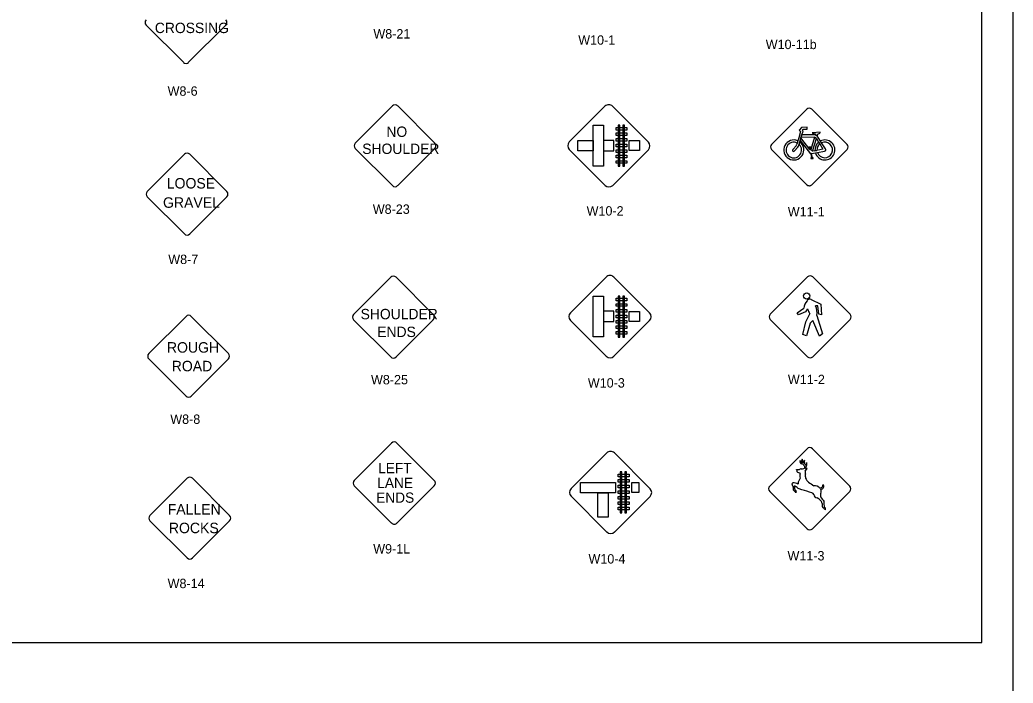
# Model space of a CAD drawing. Extents: x 42133 to 45533, y 41351 to 47951.
# Drawn here: x 44739 to 45533, y 46869 to 47400 of the extents above; entities that cross this region are included whole.
import ezdxf

# ---------------------------------------------------------------- set-up
doc = ezdxf.new("R2010")
doc.units = 0
for name, color, linetype in [('#plot_shape', 7, 'Continuous'), ('P_ODOT_PLAN_Border', 7, 'Continuous'), ('P_TRAF_SIGN_SignDetails', 7, 'Continuous')]:
    doc.layers.add(name, color=color, linetype=linetype)

msp = doc.modelspace()

# ---------------------------------------------------------------- linework, layer by layer
at = {"layer": '#plot_shape'}
msp.add_lwpolyline([(43833.34, 46851.35), (45533.34, 46851.35), (45533.34, 47951.35), (43833.34, 47951.35)], close=True, dxfattribs=at)
at = {"layer": 'P_ODOT_PLAN_Border'}
msp.add_lwpolyline([(43908.34, 46901.35), (45508.34, 46901.35), (45508.34, 47901.35), (43908.34, 47901.35)], close=True, dxfattribs=at)
at = {"layer": 'P_TRAF_SIGN_SignDetails'}
for p, q in [((44839.93, 47395.35), (44869.67, 47365.61)), ((44873.91, 47365.61), (44903.66, 47395.35)), ((45036.83, 47330.68), (45007.09, 47300.94)), ((45070.82, 47300.94), (45041.08, 47330.68)), ((45178.37, 47301.91), (45206.89, 47330.44)), ((45213.01, 47330.43), (45241.6, 47301.84)), ((45368.24, 47328.17), (45340.04, 47299.96)), ((45400.48, 47299.96), (45372.26, 47328.17)), ((45363.35, 47310.21), (45361.84, 47305.33)), ((45364.11, 47313.34), (45362.29, 47311.46)), ((45362.29, 47311.46), (45363.35, 47310.21)), ((45368.51, 47313.61), (45364.11, 47313.34)), ((45364.38, 47307.62), (45365.3, 47310.61)), ((45364.66, 47311.38), (45365.29, 47312.03)), ((45365.3, 47310.61), (45364.66, 47311.38)), ((45365.29, 47312.03), (45368.6, 47312.24)), ((45368.6, 47312.24), (45368.51, 47313.61)), ((45378.95, 47309.66), (45372.82, 47309.33)), ((45375.25, 47308.32), (45375.05, 47307.56)), ((45376.67, 47306.83), (45377.09, 47308.42)), ((45378.95, 47309.66), (45378.95, 47309.66)), ((45360.65, 47301.03), (45360.4, 47300.14)), ((45361.15, 47302.83), (45360.65, 47301.03)), ((45361.84, 47305.31), (45361.15, 47302.83)), ((45362.17, 47300), (45362.71, 47301.93)), ((45362.2, 47300.01), (45362.71, 47301.93)), ((45362.71, 47301.93), (45363.05, 47303.16)), ((45363.05, 47303.16), (45363.65, 47305.24)), ((45363.65, 47305.24), (45363.05, 47303.16)), ((45363.05, 47303.16), (45371.3, 47292.37)), ((45363.65, 47305.24), (45363.84, 47305.88)), ((45370.81, 47295.89), (45363.65, 47305.24)), ((45363.84, 47305.88), (45364.38, 47307.62)), ((45364.38, 47307.62), (45363.84, 47305.88)), ((45363.84, 47305.88), (45374.54, 47305.81)), ((45375.05, 47307.56), (45364.38, 47307.62)), ((45374.54, 47305.81), (45371.51, 47295.82)), ((45372.93, 47294.47), (45376, 47304.57)), ((45376, 47304.57), (45374.54, 47305.81)), ((45374.54, 47305.81), (45376, 47304.57)), ((45375.05, 47307.56), (45376.67, 47306.83)), ((45376.67, 47306.83), (45375.05, 47307.56)), ((45376, 47304.57), (45377.8, 47301.67)), ((45379.32, 47302.58), (45376.67, 47306.83)), ((45377.77, 47301.71), (45378.65, 47300.3)), ((45377.8, 47301.67), (45378.64, 47300.33)), ((45378.64, 47300.33), (45377.8, 47301.67)), ((45378.64, 47300.33), (45381.25, 47296.13)), ((45378.65, 47300.3), (45378.64, 47300.33)), ((45380.14, 47301.25), (45379.32, 47302.58)), ((45380.14, 47301.25), (45379.32, 47302.58)), ((45383.21, 47296.3), (45380.14, 47301.25)), ((45380.14, 47301.23), (45380.14, 47301.25)), ((45007.09, 47296.7), (45036.84, 47266.96)), ((45041.08, 47266.96), (45070.82, 47296.7)), ((45206.96, 47267.2), (45178.37, 47295.79)), ((45241.6, 47295.71), (45213.08, 47267.2)), ((45340.04, 47295.94), (45368.24, 47267.73)), ((45359.79, 47298.76), (45357.3, 47296.03)), ((45358.58, 47294.81), (45361.25, 47297.76)), ((45362.03, 47299.49), (45362.17, 47300)), ((45371.81, 47297.65), (45369.92, 47297.65)), ((45369.92, 47297.65), (45369.92, 47297.26)), ((45369.92, 47297.26), (45370.54, 47297.26)), ((45370.54, 47297.26), (45370.81, 47295.89)), ((45370.81, 47295.89), (45371.51, 47295.82)), ((45371.51, 47295.82), (45370.81, 47295.89)), ((45371.51, 47295.82), (45371.23, 47297.26)), ((45371.23, 47297.26), (45371.81, 47297.26)), ((45371.45, 47292.39), (45371.3, 47292.37)), ((45372.18, 47292.54), (45371.45, 47292.39)), ((45371.45, 47292.39), (45372.08, 47289.08)), ((45371.51, 47295.82), (45372.93, 47294.47)), ((45372.93, 47294.47), (45371.51, 47295.82)), ((45371.81, 47297.26), (45371.81, 47297.65)), ((45372.18, 47292.54), (45375.16, 47293.14)), ((45372.83, 47289.1), (45372.18, 47292.54)), ((45372.26, 47267.73), (45400.48, 47295.94)), ((45374.8, 47294.85), (45372.93, 47294.47)), ((45376.41, 47295.17), (45374.8, 47294.85)), ((45374.8, 47294.85), (45376.41, 47295.17)), ((45375.16, 47293.14), (45376.78, 47293.45)), ((45375.16, 47293.14), (45376.78, 47293.45)), ((45381.25, 47296.13), (45376.41, 47295.17)), ((45376.78, 47293.45), (45382.45, 47294.58)), ((44870.48, 47292.01), (44840.74, 47262.27)), ((44904.47, 47262.27), (44874.72, 47292.01)), ((45372.08, 47289.08), (45371.52, 47289.08)), ((45371.52, 47289.08), (45371.52, 47288.77)), ((45371.52, 47288.77), (45373.39, 47288.77)), ((45373.39, 47289.1), (45372.83, 47289.1)), ((45373.39, 47288.77), (45373.39, 47289.1)), ((44840.74, 47258.03), (44870.48, 47228.29)), ((44874.72, 47228.29), (44904.47, 47258.03)), ((45035.54, 47193.66), (45005.8, 47163.92)), ((45069.52, 47163.92), (45039.78, 47193.66)), ((45179.3, 47165.25), (45207.82, 47193.78)), ((45213.95, 47193.77), (45242.54, 47165.18)), ((45368.87, 47193.88), (45339.05, 47164.08)), ((45368.87, 47193.88), (45339.05, 47164.08)), ((45402.92, 47164.08), (45373.12, 47193.88)), ((45402.92, 47164.08), (45373.12, 47193.88)), ((45371.75, 47175.74), (45371.75, 47175.75)), ((45371.75, 47175.75), (45379.58, 47172.02)), ((45371.75, 47175.74), (45371.75, 47175.75)), ((45371.75, 47175.74), (45371.75, 47175.75)), ((45371.75, 47175.75), (45379.58, 47172.02)), ((45371.75, 47175.74), (45371.75, 47175.75)), ((45360.69, 47165.09), (45366.04, 47168.95)), ((45360.69, 47165.09), (45366.04, 47168.95)), ((45367.34, 47165.96), (45361.63, 47163.67)), ((45367.34, 47165.96), (45361.63, 47163.67)), ((45368.92, 47168.36), (45367.34, 47165.96)), ((45368.92, 47168.36), (45367.34, 47165.96)), ((45377.09, 47170.77), (45375.21, 47170.91)), ((45377.09, 47170.77), (45375.21, 47170.91)), ((45377.97, 47164), (45377.09, 47170.77)), ((45377.97, 47164), (45377.09, 47170.77)), ((45379.58, 47172.02), (45379.97, 47163.65)), ((45379.58, 47172.02), (45379.97, 47163.65)), ((44871.79, 47162.32), (44842.05, 47132.57)), ((44905.77, 47132.57), (44876.03, 47162.32)), ((45005.8, 47159.68), (45035.54, 47129.93)), ((45039.78, 47129.93), (45069.52, 47159.68)), ((45207.89, 47130.54), (45179.3, 47159.12)), ((45242.54, 47159.05), (45214.02, 47130.54)), ((45339.05, 47159.83), (45368.87, 47130.02)), ((45339.05, 47159.83), (45368.87, 47130.02)), ((45361.63, 47163.67), (45360.69, 47165.09)), ((45361.63, 47163.67), (45360.69, 47165.09)), ((45365.07, 47147.79), (45367.53, 47158)), ((45365.07, 47147.79), (45367.53, 47158)), ((45367.53, 47158), (45370.76, 47164.47)), ((45367.53, 47158), (45370.76, 47164.47)), ((45373.06, 47159.05), (45370.98, 47156.84)), ((45373.06, 47159.05), (45370.98, 47156.84)), ((45378.52, 47146.46), (45373.06, 47159.05)), ((45378.52, 47146.46), (45373.06, 47159.05)), ((45373.12, 47130.02), (45402.92, 47159.83)), ((45373.12, 47130.02), (45402.92, 47159.83)), ((45376.32, 47163.02), (45380.94, 47148.31)), ((45376.32, 47163.02), (45380.94, 47148.31)), ((45379.97, 47163.65), (45377.97, 47164)), ((45379.97, 47163.65), (45377.97, 47164)), ((45370.98, 47156.84), (45368.1, 47146.91)), ((45370.98, 47156.84), (45368.1, 47146.91)), ((45368.1, 47146.91), (45365.07, 47147.79)), ((45368.1, 47146.91), (45365.07, 47147.79)), ((45380.94, 47148.31), (45378.52, 47146.46)), ((45380.94, 47148.31), (45378.52, 47146.46)), ((44842.05, 47128.34), (44871.79, 47098.59)), ((44876.03, 47098.59), (44905.77, 47128.34)), ((45006.41, 47031.17), (45036.26, 47061.02)), ((45040.53, 47061.02), (45070.37, 47031.17)), ((45368.51, 47056.5), (45338.63, 47026.62)), ((45402.65, 47026.62), (45372.78, 47056.5)), ((45179.77, 47024.57), (45208.3, 47053.09)), ((45214.42, 47053.09), (45243.01, 47024.5)), ((45366.4, 47047.15), (45366.4, 47047.15)), ((45363.8, 47040.43), (45363.62, 47040.43)), ((44872.7, 47032.8), (44842.96, 47003.06)), ((44906.68, 47003.06), (44876.94, 47032.8)), ((45036.26, 46997.05), (45006.41, 47026.9)), ((45070.37, 47026.9), (45040.53, 46997.05)), ((45338.63, 47022.37), (45368.52, 46992.49)), ((45372.78, 46992.49), (45402.65, 47022.37)), ((45208.36, 46989.85), (45179.77, 47018.44)), ((45243.01, 47018.37), (45214.49, 46989.85)), ((44842.96, 46998.82), (44872.7, 46969.08)), ((44876.94, 46969.08), (44906.68, 46998.82))]:
    msp.add_line(p, q, dxfattribs=at)
for points in [[(45197.5, 47315.28), (45205.68, 47315.28), (45205.68, 47282.58), (45197.5, 47282.58)], [(45215.71, 47313.51), (45224.47, 47313.51), (45224.47, 47311.44), (45215.71, 47311.44)], [(45215.71, 47309.13), (45224.47, 47309.13), (45224.47, 47307.06), (45215.71, 47307.06)], [(45218.72, 47315.3), (45217.35, 47315.3), (45217.35, 47282.5), (45218.72, 47282.5)], [(45222.45, 47315.3), (45221.08, 47315.3), (45221.08, 47282.5), (45222.45, 47282.5)], [(45185.12, 47303.1), (45197.5, 47303.1), (45197.5, 47294.91), (45185.12, 47294.91)], [(45205.68, 47294.91), (45213.97, 47294.91), (45213.97, 47303.1), (45205.68, 47303.1)], [(45215.71, 47304.56), (45224.47, 47304.56), (45224.47, 47302.49), (45215.71, 47302.49)], [(45234.42, 47294.97), (45226.13, 47294.97), (45226.13, 47303.05), (45234.42, 47303.05)], [(45215.71, 47300.04), (45224.47, 47300.04), (45224.47, 47297.96), (45215.71, 47297.96)], [(45215.71, 47295.61), (45224.47, 47295.61), (45224.47, 47293.54), (45215.71, 47293.54)], [(45215.71, 47291.36), (45224.47, 47291.36), (45224.47, 47289.29), (45215.71, 47289.29)], [(45215.71, 47286.93), (45224.47, 47286.93), (45224.47, 47284.86), (45215.71, 47284.86)], [(45197.5, 47178.62), (45205.68, 47178.62), (45205.68, 47145.92), (45197.5, 47145.92)], [(45215.71, 47176.85), (45224.47, 47176.85), (45224.47, 47174.78), (45215.71, 47174.78)], [(45218.72, 47178.64), (45217.35, 47178.64), (45217.35, 47145.84), (45218.72, 47145.84)], [(45222.45, 47178.64), (45221.08, 47178.64), (45221.08, 47145.84), (45222.45, 47145.84)], [(45205.68, 47158.25), (45213.97, 47158.25), (45213.97, 47166.44), (45205.68, 47166.44)], [(45215.71, 47172.47), (45224.47, 47172.47), (45224.47, 47170.4), (45215.71, 47170.4)], [(45215.71, 47167.9), (45224.47, 47167.9), (45224.47, 47165.83), (45215.71, 47165.83)], [(45234.42, 47158.3), (45226.13, 47158.3), (45226.13, 47166.39), (45234.42, 47166.39)], [(45215.71, 47163.38), (45224.47, 47163.38), (45224.47, 47161.3), (45215.71, 47161.3)], [(45215.71, 47158.95), (45224.47, 47158.95), (45224.47, 47156.88), (45215.71, 47156.88)], [(45215.71, 47154.7), (45224.47, 47154.7), (45224.47, 47152.63), (45215.71, 47152.63)], [(45215.71, 47150.27), (45224.47, 47150.27), (45224.47, 47148.2), (45215.71, 47148.2)], [(45217.46, 47036.16), (45226.21, 47036.16), (45226.21, 47034.1), (45217.46, 47034.1)], [(45217.46, 47031.79), (45226.21, 47031.79), (45226.21, 47029.71), (45217.46, 47029.71)], [(45220.47, 47037.95), (45219.1, 47037.95), (45219.1, 47005.16), (45220.47, 47005.16)], [(45224.19, 47037.95), (45222.83, 47037.95), (45222.83, 47005.16), (45224.19, 47005.16)], [(45187.24, 47021.29), (45187.24, 47029.47), (45215.28, 47029.47), (45215.28, 47021.29)], [(45217.46, 47027.22), (45226.21, 47027.22), (45226.21, 47025.14), (45217.46, 47025.14)], [(45217.46, 47022.69), (45226.21, 47022.69), (45226.21, 47020.62), (45217.46, 47020.62)], [(45233.95, 47021.39), (45228.42, 47021.39), (45228.42, 47029.47), (45233.95, 47029.47)], [(45201.19, 47021.29), (45209.38, 47021.29), (45209.38, 47001.76), (45201.19, 47001.76)], [(45217.46, 47018.27), (45226.21, 47018.27), (45226.21, 47016.19), (45217.46, 47016.19)], [(45217.46, 47014.02), (45226.21, 47014.02), (45226.21, 47011.95), (45217.46, 47011.95)], [(45217.46, 47009.59), (45226.21, 47009.59), (45226.21, 47007.52), (45217.46, 47007.52)]]:
    msp.add_lwpolyline(points, close=True, dxfattribs=at)
msp.add_circle((45368.26, 47178.69), 2.49, dxfattribs=at)
msp.add_circle((45368.26, 47178.69), 2.49, dxfattribs=at)
for centre, radius, start, end in [((44842.04, 47397.47), 3, 135, 225), ((44901.54, 47397.47), 3, 315, 45), ((44871.79, 47367.72), 3, 225, 315), ((45038.95, 47328.56), 3, 45, 135), ((45209.95, 47327.37), 4.33, 44.98912, 135), ((45370.26, 47326.16), 2.84, 45, 135), ((45372.89, 47309.16), 0.159, 98.17141, 240.58115), ((45376.81, 47318.22), 10.02, 246.22898, 261.11843), ((45377.22, 47310.54), 2.12, 266.63911, 329.73105), ((45378.92, 47309.52), 0.138, 336.8194, 78.51671), ((45009.21, 47298.82), 3, 135, 225), ((45068.7, 47298.82), 3, 315, 45), ((45181.43, 47298.85), 4.33, 135, 225), ((45238.54, 47298.78), 4.33, 315, 44.99846), ((45357.94, 47295.5), 8, 66.40234, 53.46049), ((45357.95, 47295.43), 6.24, 64.41042, 47.13868), ((45382.81, 47295.5), 8, 129.01304, 184.65487), ((45382.81, 47295.5), 8, 197.6727, 116.33071), ((45382.66, 47295.52), 6.24, 129.99723, 183.4253), ((45382.66, 47295.52), 6.24, 199.3058, 113.79242), ((44872.6, 47289.9), 3, 45, 135), ((45342.05, 47297.95), 2.84, 135, 225), ((45357.77, 47295.23), 0.897, 122.87626, 330.77195), ((45326.47, 47314.32), 36.77, 334.95815, 337.32166), ((45328.1, 47313.66), 36.77, 334.41845, 337.32166), ((45382.66, 47295.52), 0.955, 257.41231, 57.06777), ((45398.47, 47297.95), 2.84, 315, 45), ((44842.85, 47260.15), 3, 135, 225), ((44902.35, 47260.15), 3, 315, 45), ((45038.95, 47269.07), 3, 225, 315), ((45210.02, 47270.26), 4.33, 225, 315), ((45370.26, 47269.74), 2.84, 225, 296.51146), ((45370.26, 47269.74), 2.84, 225, 315), ((44872.6, 47230.4), 3, 225, 315), ((45037.66, 47191.54), 3, 45, 135), ((45210.88, 47190.71), 4.33, 44.98912, 135), ((45370.99, 47191.76), 3.01, 45, 135), ((45370.99, 47191.76), 3.01, 45, 135), ((45377.46, 47167.77), 11.48, 141.49763, 174.1516), ((45377.46, 47167.77), 11.48, 141.49763, 174.1516), ((45371.86, 47172.6), 4.11, 133.03994, 145.50454), ((45371.86, 47172.6), 4.11, 133.03994, 145.50454), ((45370.52, 47173.55), 2.52, 60.67847, 125.47574), ((45370.52, 47173.55), 2.52, 60.67847, 125.47574), ((45182.36, 47162.19), 4.33, 135, 225), ((45401.96, 47181.56), 35.58, 201.7818, 208.71131), ((45401.96, 47181.56), 35.58, 201.7818, 208.71131), ((45363.64, 47165.25), 12.87, 349.98612, 26.05989), ((45363.64, 47165.25), 12.87, 349.98612, 26.05989), ((44873.91, 47160.2), 3, 45, 135), ((45007.91, 47161.8), 3, 135, 225), ((45067.4, 47161.8), 3, 315, 45), ((45239.47, 47162.12), 4.33, 315, 44.99846), ((45341.18, 47161.95), 3.01, 135, 225), ((45341.18, 47161.95), 3.01, 135, 225), ((45400.8, 47161.95), 3.01, 315, 45), ((45400.8, 47161.95), 3.01, 315, 45), ((44844.16, 47130.45), 3, 135, 225), ((44903.65, 47130.45), 3, 315, 45), ((45037.66, 47132.05), 3, 225, 315), ((45210.95, 47133.6), 4.33, 225, 315), ((45370.99, 47132.14), 3.01, 225, 315), ((45370.99, 47132.14), 3.01, 225, 315), ((44873.91, 47100.71), 3, 225, 315), ((45038.39, 47058.88), 3.02, 45, 135), ((45211.35, 47050.03), 4.33, 44.98912, 135), ((45370.64, 47054.38), 3.01, 45, 135), ((45365.13, 47046.46), 2.3, 162.00661, 251.6619), ((45365.14, 47047.35), 2.21, 184.61833, 248.44889), ((45368.33, 47046.5), 4.18, 160.63849, 196.77489), ((45364.94, 47047.18), 0.9, 104.4916, 128.6904), ((45368.47, 47047.56), 3.79, 172.48527, 222.52538), ((45367.22, 47045.68), 1.68, 119.26155, 203.94207), ((45373.82, 47046.15), 7.49, 172.3359, 186.45015), ((45359.27, 47039.96), 0.925, 337.24788, 353.5455), ((45363.31, 47040.27), 3.25, 191.80546, 208.12829), ((45361.33, 47049.15), 9.37, 262.97006, 277.14368), ((45359.03, 47037.77), 1.71, 9.05604, 34.3406), ((45364.19, 47037.92), 2.57, 100.35341, 131.03646), ((45364.55, 47043.34), 3.01, 254.01861, 298.60451), ((45363.53, 47041.24), 3.16, 25.04097, 74.03532), ((45365.44, 47041.8), 1.23, 296.75986, 38.60176), ((45369.21, 47045.66), 2.85, 187.15312, 233.3936), ((45374.49, 47039.25), 7.54, 149.12165, 170.71345), ((45367.99, 47039.35), 1.45, 69.71526, 130.10996), ((45357.84, 47037.43), 9.41, 353.37323, 10.50392), ((45367.76, 47037.3), 1.97, 94.50861, 109.83271), ((45361.59, 47046.9), 6.9, 329.22641, 348.3261), ((45373.15, 47036.95), 5.99, 140.95487, 157.33758), ((45365.53, 47044.67), 2.93, 328.09001, 16.56321), ((44874.82, 47030.69), 3, 45, 135), ((45008.55, 47029.03), 3.02, 135, 224.9964), ((45068.24, 47029.03), 3.02, 315.0024, 45), ((45361.33, 47038.08), 0.616, 183.90283, 254.95593), ((45352.49, 47004.51), 34.1, 72.25252, 75.25357), ((45370.56, 47027.63), 9.28, 144.45479, 175.03848), ((45374.68, 47034.89), 11.86, 172.82912, 189.02024), ((45362.29, 47036.66), 0.677, 334.53891, 28.2537), ((45374.42, 47035), 7.36, 169.42416, 196.90838), ((45378.65, 47038.21), 12.49, 205.37782, 223.17251), ((45182.83, 47021.51), 4.33, 135, 225), ((45239.94, 47021.44), 4.33, 315, 44.99846), ((45340.76, 47024.5), 3.01, 135, 225), ((45358.35, 47028.55), 1.97, 191.04363, 207.90778), ((45357.74, 47027.98), 1.34, 129.19913, 171.59733), ((44879.96, 46734.53), 559.55, 31.46479, 31.58786), ((45357.9, 47027.82), 1.56, 113.53614, 130.17573), ((45354.26, 47025.39), 3.21, 4.74862, 22.07203), ((45355.55, 47015.05), 14.31, 66.68138, 83.05631), ((45362.41, 47024.57), 5.05, 168.27427, 191.76833), ((45358.23, 47024.18), 0.99, 220.02335, 242.46173), ((45345.14, 47009.99), 18.35, 38.03075, 46.51011), ((45352.51, 47015.43), 12.81, 46.79443, 62.46415), ((45341.67, 47023.76), 17.03, 1.07241, 10.23342), ((45359.64, 47024.16), 0.946, 184.89886, 218.90977), ((45353.46, 47017.28), 8.32, 40.81938, 49.12921), ((45362.77, 47021.67), 3.19, 160.96744, 186.81682), ((45361.52, 47028.16), 0.319, 130.63384, 172.25338), ((45353.57, 47001.45), 24.56, 63.78377, 71.69097), ((45342.11, 46930.18), 95.92, 71.57357, 76.55225), ((45480.04, 47205.76), 207.89, 237.89409, 239.34832), ((45374.26, 47020.63), 6.29, 43.26709, 91.89954), ((45379.03, 47024.12), 0.841, 78.38891, 102.60428), ((45378.47, 47027.73), 2.88, 284.71934, 4.54886), ((45379.81, 47026.36), 2.2, 259.69568, 46.38052), ((45374.63, 47022.18), 5.19, 344.30358, 22.76196), ((45400.52, 47024.5), 3.01, 315, 45), ((45371.86, 47019.1), 2.16, 19.18748, 74.63905), ((45377.27, 47020.48), 3.43, 191.18736, 258.09287), ((45367.86, 47002.48), 17.01, 46.20289, 59.19223), ((45382.46, 47019.12), 3.29, 149.92752, 200.70246), ((45405.62, 47034.99), 31.29, 212.99789, 221.14214), ((45375.97, 47012.09), 4.54, 6.33338, 36.04184), ((45406.23, 47012.74), 24.23, 176.05454, 184.41662), ((45395.87, 47012.46), 15.39, 179.56561, 186.70273), ((45381.62, 47010.57), 1.04, 175.21571, 224.73326), ((45382.01, 47010.33), 1.22, 203.66766, 247.58856), ((45386.16, 47012.66), 5.77, 216.83725, 239.0448), ((45384.65, 47011.07), 2.59, 185.22157, 218.90764), ((45383.66, 47010.91), 1.8, 234.73203, 255.85706), ((45371.84, 47008.65), 11.4, 355.28436, 2.48103), ((44845.07, 47000.94), 3, 135, 225), ((44904.56, 47000.94), 3, 315, 45), ((45038.39, 46999.19), 3.02, 224.9955, 315.00225), ((45370.64, 46994.62), 3.01, 225, 315), ((45211.42, 46992.92), 4.33, 225, 315), ((44874.82, 46971.19), 3, 225, 315)]:
    msp.add_arc(centre, radius, start, end, dxfattribs=at)

# ---------------------------------------------------------------- texts
for s, height, p in [('CROSSING', 8.305, (44846.87, 47389)), ('W8-21', 7.5, (45021.68, 47384.67)), ('W10-1', 7.5, (45185.52, 47379.71)), ('W10-11b', 7.5, (45335.48, 47376.19)), ('W8-6', 7.5, (44857.09, 47338.88)), ('NO', 8.305, (45032.07, 47305.94)), ('SHOULDER', 8.305, (45012.75, 47292.29)), ('LOOSE', 8.389, (44856.4, 47264.66)), ('GRAVEL', 8.389, (44853.4, 47249.23)), ('W8-23', 7.5, (45021.2, 47244.39)), ('W10-2', 7.5, (45192.21, 47243.02)), ('W11-1', 7.5, (45353.11, 47242.37)), ('W8-7', 7.5, (44857.63, 47204.23)), ('SHOULDER', 8.305, (45011.45, 47160.05)), ('ENDS', 8.305, (45024.77, 47145.83)), ('ROUGH', 8.389, (44856.52, 47133.34)), ('ROAD', 8.389, (44860.37, 47118.41)), ('W8-25', 7.5, (45019.78, 47107.98)), ('W10-3', 7.5, (45193.2, 47105.42)), ('W11-2', 7.5, (45353.19, 47108.13)), ('W8-8', 7.5, (44859.22, 47076.35)), ('LEFT', 8.203, (45025.45, 47036.85)), ('LANE', 8.203, (45024.74, 47025.07)), ('ENDS', 8.203, (45023.84, 47013.24)), ('FALLEN', 8.389, (44857.16, 47003.83)), ('ROCKS', 8.389, (44858.08, 46988.9)), ('W9-1L', 7.5, (45021.55, 46972.65)), ('W11-3', 7.5, (45352.89, 46967.09)), ('W10-4', 7.5, (45193.72, 46964.62)), ('W8-14', 7.5, (44857.11, 46944.94))]:
    msp.add_text(s, height=height, dxfattribs=at).set_placement(p)

doc.saveas('drawing.dxf')
